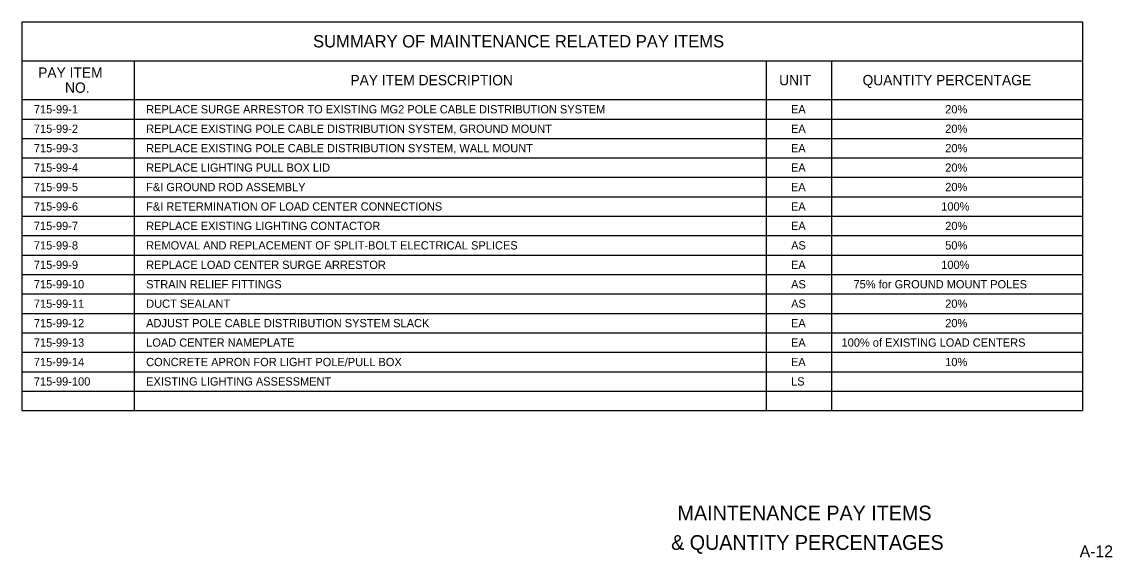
# Model space of a CAD drawing. Extents: x -55 to 2471539, y -90 to 3608906.
# Drawn here: x 587 to 1512, y -64 to 390 of the extents above; entities that cross this region are included whole.
import ezdxf

# ---------------------------------------------------------------- set-up
doc = ezdxf.new("R2010")
doc.units = 0
for name, color, linetype in [('SumBoxBorder_dp', 7, 'Continuous'), ('SumBoxLines_dp', 7, 'Continuous'), ('SumBoxLinesMin_dp', 7, 'Continuous'), ('TextLabel', 7, 'Continuous'), ('TextMisc', 7, 'Continuous'), ('TextShtNo', 7, 'Continuous')]:
    doc.layers.add(name, color=color, linetype=linetype)

msp = doc.modelspace()

# ---------------------------------------------------------------- linework, layer by layer
at = {"layer": 'SumBoxBorder_dp'}
for p, q in [((586.89, 389.94), (1486.89, 389.94)), ((586.89, 389.94), (586.89, 59.94)), ((1486.89, 389.94), (1486.89, 59.94)), ((586.89, 59.94), (1486.89, 59.94))]:
    msp.add_line(p, q, dxfattribs=at)
at = {"layer": 'SumBoxLines_dp'}
for p, q in [((586.89, 356.94), (1486.89, 356.94)), ((586.89, 356.94), (1486.89, 356.94)), ((682.14, 356.94), (682.14, 59.94)), ((682.14, 356.94), (682.14, 59.94)), ((1218.39, 356.94), (1218.39, 59.94)), ((1218.39, 356.94), (1218.39, 59.94)), ((1273.89, 356.94), (1273.89, 59.94)), ((1273.89, 356.94), (1273.89, 59.94)), ((586.89, 323.94), (1486.89, 323.94)), ((586.89, 323.94), (1486.89, 323.94))]:
    msp.add_line(p, q, dxfattribs=at)
at = {"layer": 'SumBoxLinesMin_dp'}
for p, q in [((586.89, 307.44), (1273.89, 307.44)), ((586.89, 307.44), (1486.89, 307.44)), ((586.89, 290.94), (1486.89, 290.94)), ((586.89, 290.94), (1486.89, 290.94)), ((586.89, 274.44), (1486.89, 274.44)), ((586.89, 274.44), (1486.89, 274.44)), ((586.89, 257.94), (1486.89, 257.94)), ((586.89, 257.94), (1486.89, 257.94)), ((586.89, 241.44), (1486.89, 241.44)), ((586.89, 241.44), (1486.89, 241.44)), ((586.89, 224.94), (1486.89, 224.94)), ((586.89, 224.94), (1486.89, 224.94)), ((586.89, 208.44), (1486.89, 208.44)), ((586.89, 208.44), (1486.89, 208.44)), ((586.89, 191.94), (1486.89, 191.94)), ((586.89, 191.94), (1486.89, 191.94)), ((586.89, 175.44), (1486.89, 175.44)), ((586.89, 175.44), (1486.89, 175.44)), ((586.89, 158.94), (1486.89, 158.94)), ((586.89, 158.94), (1486.89, 158.94)), ((586.89, 142.44), (1486.89, 142.44)), ((586.89, 142.44), (1486.89, 142.44)), ((586.89, 125.94), (1486.89, 125.94)), ((586.89, 125.94), (1486.89, 125.94)), ((586.89, 109.44), (1486.89, 109.44)), ((586.89, 109.44), (1486.89, 109.44)), ((586.89, 92.94), (1486.89, 92.94)), ((586.89, 92.94), (1486.89, 92.94)), ((586.89, 76.44), (1486.89, 76.44)), ((586.89, 76.44), (1486.89, 76.44))]:
    msp.add_line(p, q, dxfattribs=at)

# ---------------------------------------------------------------- texts
at = {"layer": 'TextLabel'}
for s, height, p in [('SUMMARY OF MAINTENANCE RELATED PAY ITEMS', 10.5, (833.99, 368.19)), ('PAY ITEM', 8.75, (600.78, 342.44)), ('PAY ITEM DESCRIPTION', 8.75, (865.73, 336.07)), ('UNIT', 8.75, (1229.43, 336.07)), ('QUANTITY PERCENTAGE', 8.75, (1300.21, 336.07)), ('NO.', 8.75, (623.56, 329.69)), ('715-99-1', 7, (597.14, 312.19)), ('REPLACE SURGE ARRESTOR TO EXISTING MG2 POLE CABLE DISTRIBUTION SYSTEM', 7, (692.39, 312.19)), ('EA', 7, (1239.46, 312.19)), ('20%', 7, (1370.36, 312.19)), ('715-99-2', 7, (597.14, 295.69)), ('REPLACE EXISTING POLE CABLE DISTRIBUTION SYSTEM, GROUND MOUNT', 7, (692.39, 295.69)), ('EA', 7, (1239.46, 295.69)), ('20%', 7, (1370.36, 295.69)), ('715-99-3', 7, (597.14, 279.19)), ('REPLACE EXISTING POLE CABLE DISTRIBUTION SYSTEM, WALL MOUNT', 7, (692.39, 279.19)), ('EA', 7, (1239.46, 279.19)), ('20%', 7, (1370.36, 279.19)), ('715-99-4', 7, (597.14, 262.69)), ('REPLACE LIGHTING PULL BOX LID', 7, (692.39, 262.69)), ('EA', 7, (1239.46, 262.69)), ('20%', 7, (1370.36, 262.69)), ('715-99-5', 7, (597.14, 246.19)), ('F&I GROUND ROD ASSEMBLY', 7, (692.39, 246.19)), ('EA', 7, (1239.46, 246.19)), ('20%', 7, (1370.36, 246.19)), ('715-99-6', 7, (597.14, 229.69)), ('F&I RETERMINATION OF LOAD CENTER CONNECTIONS', 7, (692.39, 229.69)), ('EA', 7, (1239.46, 229.69)), ('100%', 7, (1366.97, 229.69)), ('715-99-7', 7, (597.14, 213.19)), ('REPLACE EXISTING LIGHTING CONTACTOR', 7, (692.39, 213.19)), ('EA', 7, (1239.46, 213.19)), ('20%', 7, (1370.36, 213.19)), ('715-99-8', 7, (597.14, 196.69)), ('REMOVAL AND REPLACEMENT OF SPLIT-BOLT ELECTRICAL SPLICES', 7, (692.39, 196.69)), ('AS', 7, (1239.61, 196.69)), ('50%', 7, (1370.36, 196.69)), ('715-99-9', 7, (597.14, 180.19)), ('REPLACE LOAD CENTER SURGE ARRESTOR', 7, (692.39, 180.19)), ('EA', 7, (1239.46, 180.19)), ('100%', 7, (1366.97, 180.19)), ('715-99-10', 7, (597.14, 163.69)), ('STRAIN RELIEF FITTINGS', 7, (692.39, 163.69)), ('AS', 7, (1239.61, 163.69)), ('75% for GROUND MOUNT POLES', 7, (1292.55, 163.69)), ('715-99-11', 7, (597.14, 147.19)), ('DUCT SEALANT', 7, (692.39, 147.19)), ('AS', 7, (1239.61, 147.19)), ('20%', 7, (1370.36, 147.19)), ('715-99-12', 7, (597.14, 130.69)), ('ADJUST POLE CABLE DISTRIBUTION SYSTEM SLACK', 7, (692.39, 130.69)), ('EA', 7, (1239.46, 130.69)), ('20%', 7, (1370.36, 130.69)), ('715-99-13', 7, (597.14, 114.19)), ('LOAD CENTER NAMEPLATE', 7, (692.39, 114.19)), ('EA', 7, (1239.46, 114.19)), ('100% of EXISTING LOAD CENTERS', 7, (1282.39, 114.19)), ('715-99-14', 7, (597.14, 97.69)), ('CONCRETE APRON FOR LIGHT POLE/PULL BOX', 7, (692.39, 97.69)), ('EA', 7, (1239.46, 97.69)), ('10%', 7, (1370.36, 97.69)), ('715-99-100', 7, (597.14, 81.19)), ('EXISTING LIGHTING ASSESSMENT', 7, (692.39, 81.19)), ('LS', 7, (1239.61, 81.19))]:
    msp.add_text(s, height=height, dxfattribs=at).set_placement(p)
at = {"layer": 'TextMisc'}
for s, p in [('MAINTENANCE PAY ITEMS', (1143.25, -33.24)), ('& QUANTITY PERCENTAGES', (1137.8, -58.24))]:
    msp.add_text(s, height=12.5, dxfattribs=at).set_placement(p)
at = {"layer": 'TextShtNo'}
msp.add_text(' A-12 ', height=10, dxfattribs=at).set_placement((1480.74, -64.49))

doc.saveas('drawing.dxf')
